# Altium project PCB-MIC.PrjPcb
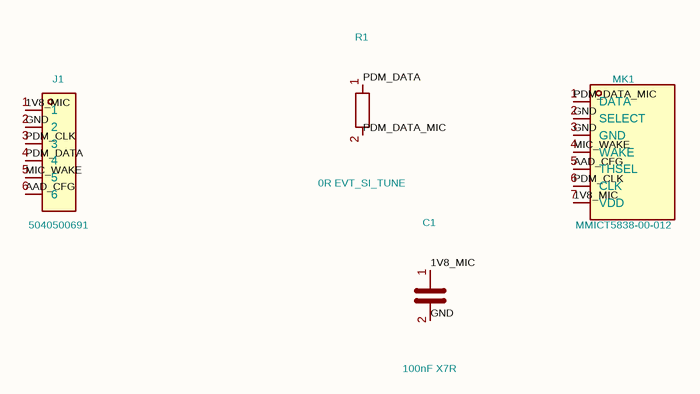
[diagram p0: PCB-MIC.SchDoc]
1 sheet, 4 parts. Net scope: global (net labels, ports and power ports of the same name join across sheets).
Board file: PCB-MIC.PcbDoc

## Sheet PCB-MIC.SchDoc
size 297 x 209 mm

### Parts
C1  100nF X7R  [C_0402_1005Metric]
J1  5040500691  [Molex_5040500691]
MK1  MMICT5838-00-012  [T5838_RevA]
R1  0R EVT_SI_TUNE  [R_0402_1005Metric]

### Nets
1V8_MIC: C1.1 J1.1 MK1.7(VDD)
AAD_CFG: J1.6 MK1.5(THSEL)
GND: C1.2 J1.2 MK1.2(SELECT) MK1.3(GND)
MIC_WAKE: J1.5 MK1.4(WAKE)
PDM_CLK: J1.3 MK1.6(CLK)
PDM_DATA: J1.4 R1.1
PDM_DATA_MIC: MK1.1(DATA) R1.2

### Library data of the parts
C1 = C
R1 = R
